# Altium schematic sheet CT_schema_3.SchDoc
size 203 x 169 mm
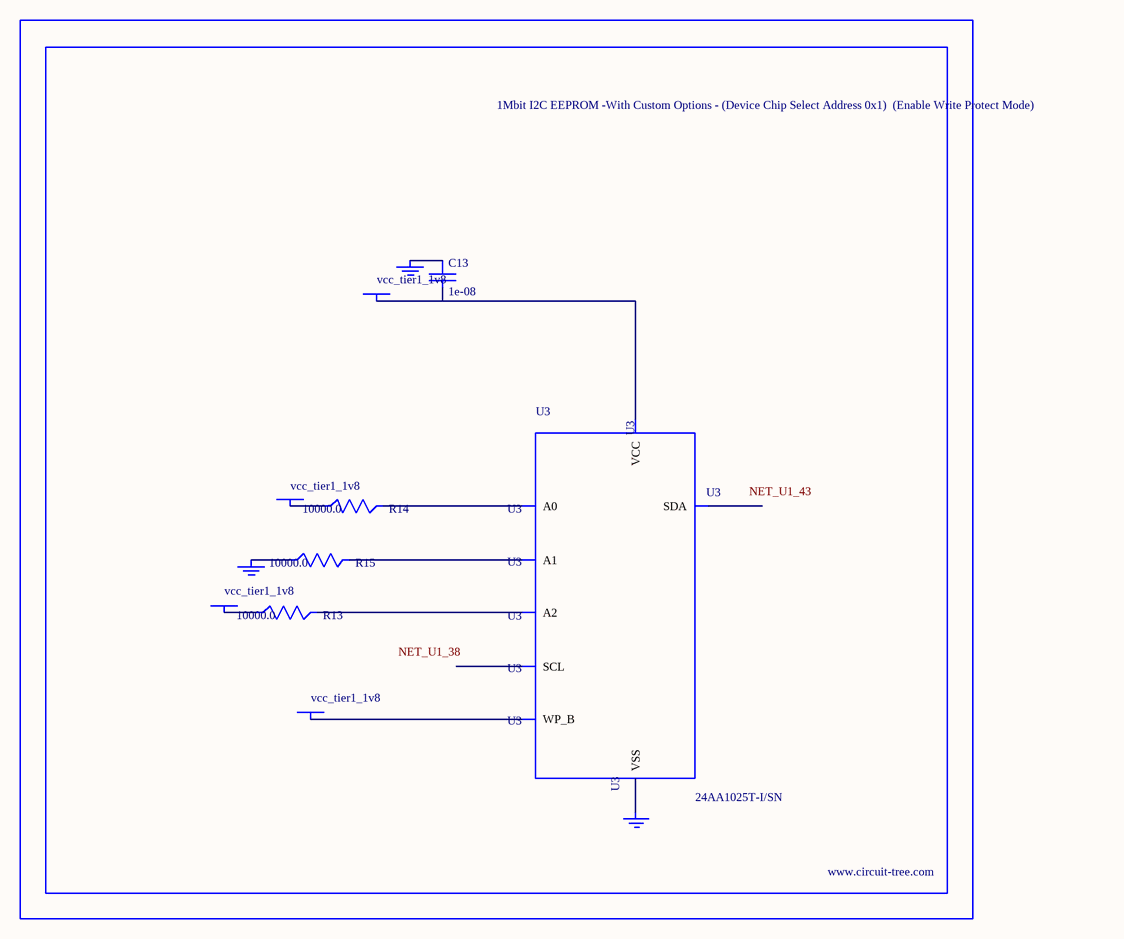
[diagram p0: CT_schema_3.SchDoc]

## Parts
BORDER2  (no value)
C13  1e-08  [C0402]
GND_INSTANCE_2_0  (no value)
GND_INSTANCE_2_1  (no value)
GND_INSTANCE_2_2  (no value)
POWER_INSTANCE_2_0  vcc_tier1_1v8
POWER_INSTANCE_2_1  vcc_tier1_1v8
POWER_INSTANCE_2_2  vcc_tier1_1v8
POWER_INSTANCE_2_3  vcc_tier1_1v8
R13  10000.0  [R0603]
R14  10000.0  [R0603]
R15  10000.0  [R0603]
U3  24AA1025T-I/SN  [SOIC-8]

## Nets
NetC13_1: C13.1 GND_INSTANCE_2_1.0(GND)
NetC13_2: C13.2 POWER_INSTANCE_2_3.0(PWR) U3.8(VCC)
NetGND_INSTANCE_2_0_0: GND_INSTANCE_2_0.0(GND) R15.1
NetGND_INSTANCE_2_2_0: GND_INSTANCE_2_2.0(GND) U3.4(VSS)
NetPOWER_INSTANCE_2_0_0: POWER_INSTANCE_2_0.0(PWR) R14.1
NetPOWER_INSTANCE_2_1_0: POWER_INSTANCE_2_1.0(PWR) R13.1
NetPOWER_INSTANCE_2_2_0: POWER_INSTANCE_2_2.0(PWR) U3.7(WP_B)
NetR13_2: R13.2 U3.3(A2)
NetR14_2: R14.2 U3.1(A0)
NetR15_2: R15.2 U3.2(A1)

Not connected (* = marked no-connect by the designer): U3 5(SDA) 6(SCL)

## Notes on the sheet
- Labels drawn without touching a wire or pin: NET_U1_38, NET_U1_43

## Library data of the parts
BORDER2 = BORDER_PAGE2
C13 = C0402C103K3RAC
GND_INSTANCE_2_0-GND_INSTANCE_2_2 = GND
POWER_INSTANCE_2_0-POWER_INSTANCE_2_3 = PWR
R13-R15 = RC0603JR-0710KL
